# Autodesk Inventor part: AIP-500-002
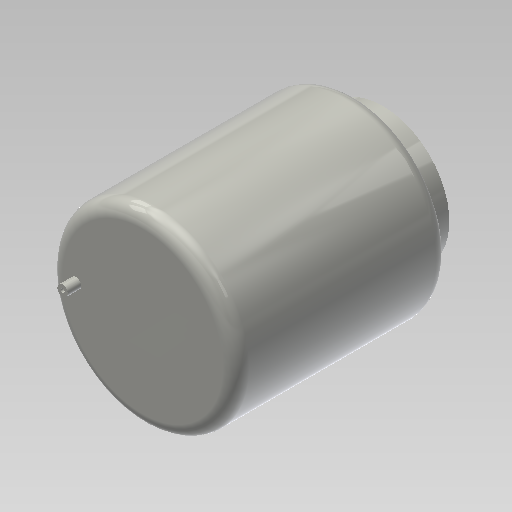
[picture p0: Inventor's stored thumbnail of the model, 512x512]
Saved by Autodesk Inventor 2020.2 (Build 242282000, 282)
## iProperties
Created: 2014-06
Part Number: AIP-500-002
Material: Ogólny
Document SubType Name: Modeling
Designer: F.Stasiak
Density: 1 g/cm^3
Appearance: Gładkie - w kolorze kości słoniowej
Catalog Web Link: www.expertbooks.pl
Manager: www.cadconsulting.pl
Company: Fabian Stasiak CAD Consulting
Author: F.Stasiak
Subject: Zbiór ćwiczeń. Autodesk Inventor 2020. Kurs Professional
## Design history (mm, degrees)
sketch "Szkic1"
  geometry: C1 r 350 at (0, 0); 1 further point
  constraints: 1 centre point, 1 coincident
  dimensions: "d0" = 700 diameter of C1
extrude "Wyciągnięcie proste1" new body sketch "Szkic1" distance "d1" = 800; taper "d2" = 0 deg
fillet "Zaokrąglenie1" dims "d3" = 50
sketch "Szkic2"
  geometry: C1 r 300 at (0, 0) reference; C2 r 250 at (0, 0)
  constraints: 1 centre point, 1 coincident
  dimensions: "d4" = 500 diameter of C2
extrude "Wyciągnięcie proste2" join sketch "Szkic2" distance "d5" = 100; taper "d6" = 0 deg
sketch "Szkic3"
  geometry: C1 r 300 at (0, 0) reference; C2 r 20 at (-250, 0)
  constraints: 1 centre point
  dimensions: "d7" = 40 diameter of C2; "d8" = 250 distance of C1.centre C2.centre
extrude "Wyciągnięcie proste3" join sketch "Szkic3" distance "d9" = 50; taper "d10" = 0 deg
hole "Otwór1" diameter "d13" = 16; stored, may be unused: countersink angle "d17" = 90 deg, drill point angle "d19" = 118 deg; dims "d11" = 10, "d12" = 10, "d14" = 6, "d15" = 4, "d16" = 2, "d18" = 15
node "Bryła1"
